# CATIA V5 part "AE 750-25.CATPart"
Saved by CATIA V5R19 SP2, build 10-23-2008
Part number: AE 750-25
Bounding box of the stored display mesh (mm): x -24.865 to 24.865, y -24.997 to 24.997, z 0 to 100
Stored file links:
  C:\Users\Bora\Desktop\3D Katı model\AE serisi\AE 750\AE 750-25.CATPart
  C:\Program Files\Dassault Systemes\B19\intel_a\reffiles\standard\MetricThickPitch.txt
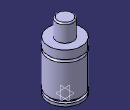
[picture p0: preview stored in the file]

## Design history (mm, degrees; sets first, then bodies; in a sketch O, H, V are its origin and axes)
Body1 (main body)
  Sketch1 on yz-plane, origin (0, 0, 0), H (0, 1, 0), V (0, 0, 1)
    point P1 (25, 57.5)
    point P8 (25, 61.5)
    point P9 (12.5, 98)
    point P11 (12.5, 98)
    point P13 (25, 61.5)
    point P14 (25, 57.5)
    line L1 (25, 57.5) -> (25, 8)
    line L2 (25, 4) -> (25, 0)
    line L3 (21.5, 8) -> (21.5, 4)
    line L4 (25, 74) -> (25, 61.5)
    line L5 (12.5, 98) -> (12.5, 74)
    arc A1 centre (10.5, 98) radius 2 from (12.5, 98) to (10.5, 100) ccw
    arc A2 centre (25, 59.5) radius 2 from (25, 61.5) to (25, 57.5) ccw
    line L6 (10.5, 100) -> (0, 100)
    point P15 (0, 100)
    line L7 (12.5, 74) -> (25, 74)
    line L8 (0, 0) -> (25, 0)
    line L9 (21.5, 8) -> (25, 8)
    line L10 (21.5, 4) -> (25, 4)
    tangency: L6 A1
    coincidence: P15 V, P1 P14, P8 P13, P9 P11
    horizontal: L7 H, L8 H, L9 H, L10 H
  Shaft1: profile Sketch1, axis Sketch1.V, angle 360
  Sketch2 on face of Shaft1 from Sketch1.L8, origin (0, 0, 0), H (1, 0, 0), V (0, -1, 0)
    point P1 (10, 0)
    distance P1 V = 10
  Hole1: placed by Sketch2, at (10, 0, 0) direction (0, 0, 1), diameter 6.647, depth 13, threaded "M8", thread diameter 8, thread depth 13, pitch 1.25
  CircPattern1: of Hole1, instances 2, angular step 180, axis from xy-plane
